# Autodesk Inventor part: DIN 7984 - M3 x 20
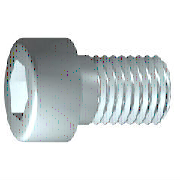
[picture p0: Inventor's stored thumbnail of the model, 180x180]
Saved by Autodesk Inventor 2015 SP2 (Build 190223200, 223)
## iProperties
Created: 2012-02
Part Number: DIN 7984 - M3 x 20
Material: Stahl, weich
Description: Zylinderkopfschraube
Document SubType Name: Modeling
Standard: DIN 7984
Designer: Hübner
Standard Revision: 1985
Standards Organization: DIN
Language: de-DE
Size Designation: M3 x 20
Categories: <MemberInstance><Categories><Category DisplayName="Verbindungselemente" InternalName="e4da775c-781d-43d5-af7c-5136215cf5a6" Mnemonic="FSTN"><Category DisplayNam
Density: 7.85 g/cm^3
Appearance: Halbpoliert
IsCustomPart: 0
Author: Hübner
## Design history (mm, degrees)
sketch "Skizze1"
  geometry: L1 (0.167, 0)-(20, 0); L2 (20, 0)-(20, 1.5); L3 (20, 1.5)-(8, 1.5); L4 (8, 1.5)-(7.693, 1.5); L5 (7.693, 1.5)-(0, 1.5); L6 (0, 1.5)-(0, 2.75); L7 (0, 2.75)-(-2, 2.75); L8 (-2, 2.75)-(-2, 1.155); L9 (-2, 1.155)-(-0.5, 1.155); L10 (-0.5, 1.155)-(0.167, 0); L11 (-6.4, 0)-(24.4, 0) reference; L12 (0, -0.55)-(0, 3.3) reference; L13 (8, 1.5)-(0, 1.5)
  constraints: 22 end point, 6 parallel, 2 collinear, 2 perpendicular, 1 horizontal, 1 point on line
  dimensions: "d1" = 12 distance from line of L3.end L2 (= GEL); "d2" = 0.30683 distance of L4.end L3.end (computed from GAL); "d3" = 2 distance between parallel lines of L8 L6 (= KOH); "d4" = 1.5 distance of L8.end L9.end (= INTI); "d5" = 60 deg angle of L10 L1; "d6" = 3 diameter of L3 L1 (= GD); "d7" = 3 diameter of L5 L1 (= BDM); "d8" = 2.3094 diameter of L9 L1 (= 1.1547 x SW); "d9" = 5.5 diameter of L7 L1 (= KOD); "d26" = 20 distance between parallel lines of L12 L2 (= NLG)
revolve "Körper" sketch "Skizze1" stored, may be unused: angle "d10" = 90 deg
sketch "Skizze2"
  geometry: L1 (0, -3.85)-(0, 3.85) reference; L2 (-3.85, 0)-(3.85, 0) reference; L3 (1.155, 0)-(0.577, -1); L4 (0.577, -1)-(-0.577, -1); L5 (-0.577, -1)-(-1.155, 0); L6 (-1.155, 0)-(-0.577, 1); L7 (-0.577, 1)-(0.577, 1); L8 (0.577, 1)-(1.155, 0); 2 further points
  constraints: 12 end point, 1 coincident, 1 horizontal alignment, 1 point on line, 12 other
extrude "Loch" join sketch "Skizze2" stored distance "d11" = 10; taper "d12" = 0 deg
workplane "Work Plane1"
fillet "Fillet2" dims "d30" = 0.1 (= R)
body "Solid1"
fillet "Rundung1" dims "d17" = 0.3 (= RR)
feature "Gewinde" dims "d13" = 12 (= GEL), "d14" = 0
chamfer "Fase1" distance "d15" = 0.30673 (= -0.5 x SPD + 0.5 x GD); stored, may be unused: second distance "d16" = 0.30673 (= GUL), angle "d27" = 45 deg
other parameters: "GD" = 3 (= NND) [user parameter; used in 2 equation terms], "NLG" = 20 [user parameter; used in 1 equation term], "GEL" = 12 [user parameter; used in 2 equation terms], "KOD" = 5.5 [user parameter; used in 1 equation term], "KOH" = 2 [user parameter; used in 1 equation term], "INTI" = 1.5 [user parameter; used in 1 equation term], "GAL" = 0.30673 (= 0.61345 x PTC) [user parameter; used in 1 equation term], "GUL" = 0.30673 (= 0.61345 x PTC) [user parameter; used in 1 equation term], "BDM" = 3 (= NND) [user parameter; used in 1 equation term], "SW" = 2 [user parameter; used in 2 equation terms], "RR" = 0.3 [user parameter; used in 1 equation term], "SPD" = 2.38655 (= NND - 1.2269 x PTC) [user parameter; used in 1 equation term], "d19" = 0, "d28" = 0, "d29" = 0, "R" = 0.1 [user parameter; used in 1 equation term], "TOA" = 30 deg [user parameter], "GD1" = 2.38655 (= THREADDIA - 1.2269 x PTC) [user parameter], "THREADDIA" = 3 [user parameter; used in 1 equation term], "FAWI" = 45 deg [user parameter], "ANG" = 120 deg [user parameter], "PTC" = 0.5 [user parameter; used in 5 equation terms], "NND" = 3 [user parameter; used in 3 equation terms], "E0" = 2.31 (= 1.155 x SW) [user parameter]
